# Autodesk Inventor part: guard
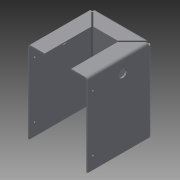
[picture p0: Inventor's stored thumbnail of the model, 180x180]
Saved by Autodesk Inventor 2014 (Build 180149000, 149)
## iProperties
Created: 2008-09
Part Number: guard
Material: Generic
Document SubType Name: Sheet Metal
Designer: Autodesk
Density: 1 g/cm^3
Sheet Metal Rule: Default_mm
Flat Pattern Width: 14.5524 cm
Flat Pattern Length: 27.7048 cm
Flat Pattern Area: 403.171 cm^2
Appearance: Default
Author: Autodesk
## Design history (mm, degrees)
node "Contour Flange1"
  sketch "Sketch1"
    geometry: L1 (0, 0)-(-86, 0) reference; L2 (-86, 0)-(-86, 95); L3 (-86, 95)-(0, 95); L4 (0, 95)-(0, 0)
    constraints: 8 end point, 2 perpendicular, 1 horizontal, 1 parallel, 2 other
    dimensions: "d0" = 95 distance of L1.end L2.end
node "Flange3"
sketch "Sketch6"
  geometry: L1 (104, 53)-(104, 8); L2 (104, 8)-(19, 8); L3 (120, 0)-(0, 0) reference; C1 r 5.5 at (104, 53) reference; 3 further points
  constraints: 4 end point, 3 coincident, 1 centre point, 1 perpendicular, 1 vertical, 2 other
  dimensions: "d41" = 85 distance of L1.end L2.end; "d42" = 8 distance between parallel lines of L2 L3
feature "iFeature1:3"
feature "iFeature1:4"
workplane "Work Plane2"
mirror "Mirror1"
body "Solid1"
face "Plate1" dims "d1" = 2 (= BendReliefWidth), "d2" = 1 (= BendReliefDepth), "d3" = 4 (= MinimumRemnant), "d4" = 2 (= BendRadius), "d5" = 120, "d6" = 2 (= BendRadius), "d7" = 2, "d8" = 8 (= CornerReliefSize), "d9" = 2 (= GapSize), "d10" = 2 (= JacobiRadiusSize), "SeamGap" = 0.01, "Thickness" = 2 (derived)
bend "Bend1" dims "d1" = 2 (= BendReliefWidth), "d2" = 1 (= BendReliefDepth), "d3" = 4 (= MinimumRemnant), "d4" = 2 (= BendRadius), "d6" = 2 (= BendRadius), "d7" = 2, "SeamGap" = 0.01, "Thickness" = 2 (derived)
feature "Corner1" dims "d7" = 2, "d8" = 8 (= CornerReliefSize), "d9" = 2 (= GapSize), "d10" = 2 (= JacobiRadiusSize)
sketch "Sketch4"
  geometry: L1 through (0, 46.5) direction (0, -1); L2 through (10.5, 0) direction (1, 1.96e-48); L3 (21, 0)-(21, 93); L4 (21, 93)-(0, 93)
  constraints: 6 end point, 1 horizontal, 1 perpendicular, 1 vertical
face "Plate4" dims "d31" = 2 (= BendReliefWidth), "d32" = 1 (= BendReliefDepth), "d33" = 4 (= MinimumRemnant), "d34" = 2 (= BendRadius), "d35" = 25, "d36" = 90 deg, "d37" = 2 (= BendRadius), "d38" = 8 (= CornerReliefSize), "d39" = 2 (= GapSize), "d40" = 2 (= JacobiRadiusSize), "SeamGap" = 0.01, "Thickness" = 2 (derived)
bend "Bend4" dims "d31" = 2 (= BendReliefWidth), "d32" = 1 (= BendReliefDepth), "d33" = 4 (= MinimumRemnant), "d34" = 2 (= BendRadius), "d35" = 25, "d36" = 90 deg, "d37" = 2 (= BendRadius), "SeamGap" = 0.01, "Thickness" = 2 (derived)
feature "Corner4" dims "d35" = 25, "d36" = 90 deg, "d38" = 8 (= CornerReliefSize), "d39" = 2 (= GapSize), "d40" = 2 (= JacobiRadiusSize)
feature "Definition1"
other parameters: "BendRadius" = 2 (= Thickness), "BendReliefWidth" = 2 (= Thickness), "BendReliefDepth" = 1 (= 0.5 x Thickness), "CornerReliefSize" = 8 (= 4 x Thickness), "MinimumRemnant" = 4 (= 2 x Thickness), "TransitionRadius" = 2 (= BendRadius), "JacobiRadiusSize" = 2 (= BendRadius), "GapSize" = 2 (= Thickness), "d55" = 0, "d57" = 0, "d58" = 43, "BendRadius" = 2, "BendReliefDepth" = 1, "BendReliefWidth" = 2, "CornerReliefSize" = 8, "GapSize" = 2, "JacobiRadiusSize" = 2, "MinimumRemnant" = 4, "Thickness" = 2, "TransitionRadius" = 2
